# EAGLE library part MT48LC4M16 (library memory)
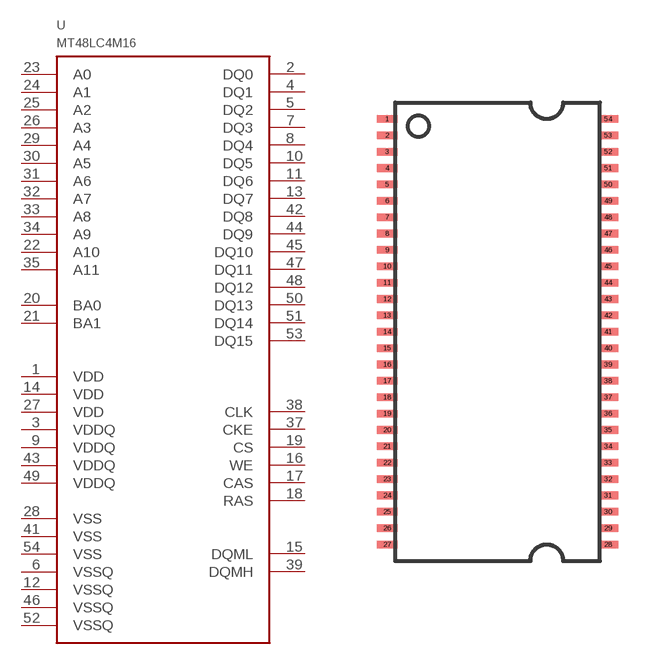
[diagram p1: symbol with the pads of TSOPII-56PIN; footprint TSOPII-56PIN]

Designator prefix U

## MT48LC4M16P  [TSOPII-56PIN]
1  VDD  pwr
2  DQ0
3  VDDQ  pwr
4  DQ1
5  DQ2
6  VSSQ  pwr
7  DQ3
8  DQ4
9  VDDQ  pwr
10  DQ5
11  DQ6
12  VSSQ  pwr
13  DQ7
14  VDD  pwr
15  DQML  in
16  WE  in
17  CAS  in
18  RAS  in
19  CS  in
20  BA0  in
21  BA1  in
22  A10  in
23  A0  in
24  A1  in
25  A2  in
26  A3  in
27  VDD  pwr
28  VSS  pwr
29  A4  in
30  A5  in
31  A6  in
32  A7  in
33  A8  in
34  A9  in
35  A11  in
37  CKE  in
38  CLK  in
39  DQMH  in
41  VSS  pwr
42  DQ8
43  VDDQ  pwr
44  DQ9
45  DQ10
46  VSSQ  pwr
47  DQ11
48  DQ12
49  VDDQ  pwr
50  DQ13
51  DQ14
52  VSSQ  pwr
53  DQ15
54  VSS  pwr

## Footprint TSOPII-56PIN (pad centres in mm)
TS056/TSR056 56-Pin Thin Small Outline Package (TSOP) Standard Pinout Source: www.amd.com .. 26191.pdf
smd 1 x 0.375: 1 -5.4,10.4; 2 -5.4,9.6; 3 -5.4,8.8; 4 -5.4,8; 5 -5.4,7.2; 6 -5.4,6.4; 7 -5.4,5.6; 8 -5.4,4.8; 9 -5.4,4; 10 -5.4,3.2; 11 -5.4,2.4; 12 -5.4,1.6; 13 -5.4,0.8; 14 -5.4,0; 15 -5.4,-0.8; 16 -5.4,-1.6; 17 -5.4,-2.4; 18 -5.4,-3.2; 19 -5.4,-4; 20 -5.4,-4.8; 21 -5.4,-5.6; 22 -5.4,-6.4; 23 -5.4,-7.2; 24 -5.4,-8; 25 -5.4,-8.8; 26 -5.4,-9.6; 27 -5.4,-10.4; 28 5.4,-10.4; 29 5.4,-9.6; 30 5.4,-8.8; 31 5.4,-8; 32 5.4,-7.2; 33 5.4,-6.4; 34 5.4,-5.6; 35 5.4,-4.8; 36 5.4,-4; 37 5.4,-3.2; 38 5.4,-2.4; 39 5.4,-1.6; 40 5.4,-0.8; 41 5.4,0; 42 5.4,0.8; 43 5.4,1.6; 44 5.4,2.4; 45 5.4,3.2; 46 5.4,4; 47 5.4,4.8; 48 5.4,5.6; 49 5.4,6.4; 50 5.4,7.2; 51 5.4,8; 52 5.4,8.8; 53 5.4,9.6; 54 5.4,10.4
